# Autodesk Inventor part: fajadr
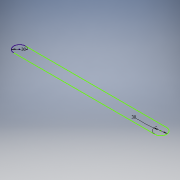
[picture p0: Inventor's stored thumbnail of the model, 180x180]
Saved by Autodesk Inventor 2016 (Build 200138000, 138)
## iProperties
Created: 2016-06
Part Number: fajadr
Material: Genérico
Document SubType Name: Modeling
Designer: adm
Density: 1 g/cm^3
Appearance: Valor por defecto
Author: adm
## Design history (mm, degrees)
sketch "Boceto1"
  geometry: 1 further point
node "Plano de trabajo1"
sketch "Boceto3"
  geometry: L1 (0, 15)-(360, 15); L2 (0, -15)-(360, -15); A1 r 15 centre (0, 0) between (0, 15) and (0, -15); A2 r 15 centre (360, 0) between (360, -15) and (360, 15); 1 further point
  constraints: 4 end point, 4 point on circle, 2 centre point, 1 coincident, 1 horizontal, 1 tangent
  dimensions: "d1" = 30 diameter of A1; "d2" = 30 diameter of A2
